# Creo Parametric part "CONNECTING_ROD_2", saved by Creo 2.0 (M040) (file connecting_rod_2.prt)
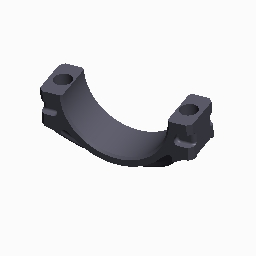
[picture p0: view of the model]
Units: millimeter Kilogram Sec (mmKs); MM, KILOGRAM, SECS

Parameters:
  MATERIAL = "ST37"

Other parameters: D82, D144, D145, D131, D140, D114, D113

Created from: INLBS_PART_SOLID.PRT

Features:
  1. datum plane "SIDE", "RIGHT"
  2. datum plane "DTM1", "TOP"
  3. datum plane "DTM2", "FRONT"
  4. coordinate system "ORIGIN"
  5. datum axis "CRANKSHAFT_AXIS"
  6. datum point "CON_BRG"
  7. datum axis "CON_BOLT_AXIS_1"
  8. datum axis "CON_BOLT_AXIS_2"
  9. extrusion "Extrude 1", "Section 1"
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
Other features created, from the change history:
  group "COPIED_GROUP" (2 times)
  datum plane "DTM1" (2 times)
  datum plane "DTM2" (2 times)
  datum plane "DTM3" (2 times)
  coordinate system "CS0" (2 times)
  datum axis "CRANKSHAFT_AXIS" (2 times)
  datum axis "CON_BUSHING_AXIS" (3 times)
  datum axis "CON_BOLT_AXIS_1" (2 times)
  datum axis "CON_BOLT_AXIS_2" (2 times)
  datum point "Datum Point id 56" (2 times)
  sketch "Sketch 1" (2 times)
  sketch "Sketch 2" (2 times)
  extrusion "Extrude 1" (2 times)
  extrusion "Extrude 2" (3 times)
  round "Round 1" (2 times)
  round "Round 2" (2 times)
  round "Round 3" (2 times)
  extruded cut "Extrude 3" (3 times)
  round "Round id 235" (2 times)
  hole "Hole 1" (3 times)
  hole "Hole 2" (3 times)
  chamfer "Chamfer 1" (2 times)
  chamfer "Chamfer 2" (3 times)
  extruded cut "Extrude 4" (3 times)
  mirror "Mirror 1" (2 times)
  extruded cut "Extrude 5" (3 times)
  round "Round 4" (2 times)
  round "Round 5" (2 times)
  round "Round 6" (2 times)
  round "Round 7" (2 times)
  group "LOCAL_GROUP" (2 times)
  extruded cut "Extrude 6" (2 times)
  round "Round 8" (2 times)
  round "Round 9" (2 times)
  round "Round 10" (2 times)
  mirror "Mirror 2" (2 times)
  group "LOCAL_GROUP_1" (2 times)
  extruded cut "Extrude 7" (2 times)
  round "Round 11" (2 times)
  round "Round 12" (2 times)
  round "Round 13" (2 times)
  datum axis "A_10" (2 times)
  datum axis "A_11" (2 times)
  datum plane "DTM4"
  datum plane "DTM5"
  datum axis "A_12"
  datum axis "A_13" (2 times)
  mirror "Mirror 3"
  datum plane "DTM6"
  datum plane "DTM8"
  feature "Offset 1"
  round "Round id 2692"
  hole "Hole 3"
  round "Round id 2730"
  round "Round id 2731"
  round "Round id 2855"
  round "Round id 2856"
  round "Round id 2857"
  round "Round id 2858"
  round "Round id 2859"
  round "Round id 2860"
  chamfer "Chamfer 3" (2 times)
